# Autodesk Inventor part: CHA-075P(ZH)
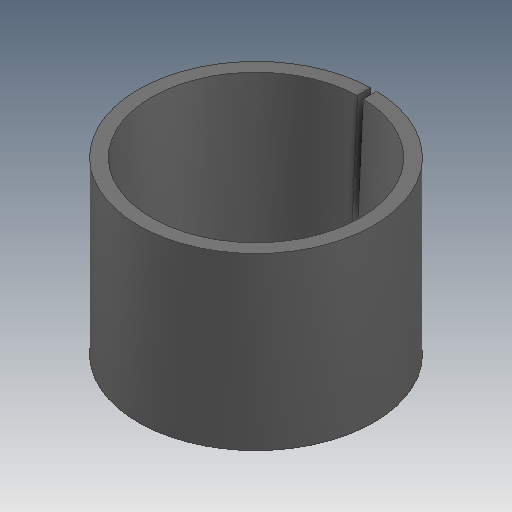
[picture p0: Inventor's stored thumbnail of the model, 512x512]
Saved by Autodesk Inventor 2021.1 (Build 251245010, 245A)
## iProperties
Created: 2021-05
Part Number: CHA-075P(ZH)
Material: Ogólny
Document SubType Name: Modeling
Designer: user
Density: 1 g/cm^3
Appearance: Domyślna
Author: user
Revision Number: ÈÎºÎ
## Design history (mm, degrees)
feature "ÇÐ³ý-À­Éì4"
node "Bryła1"
